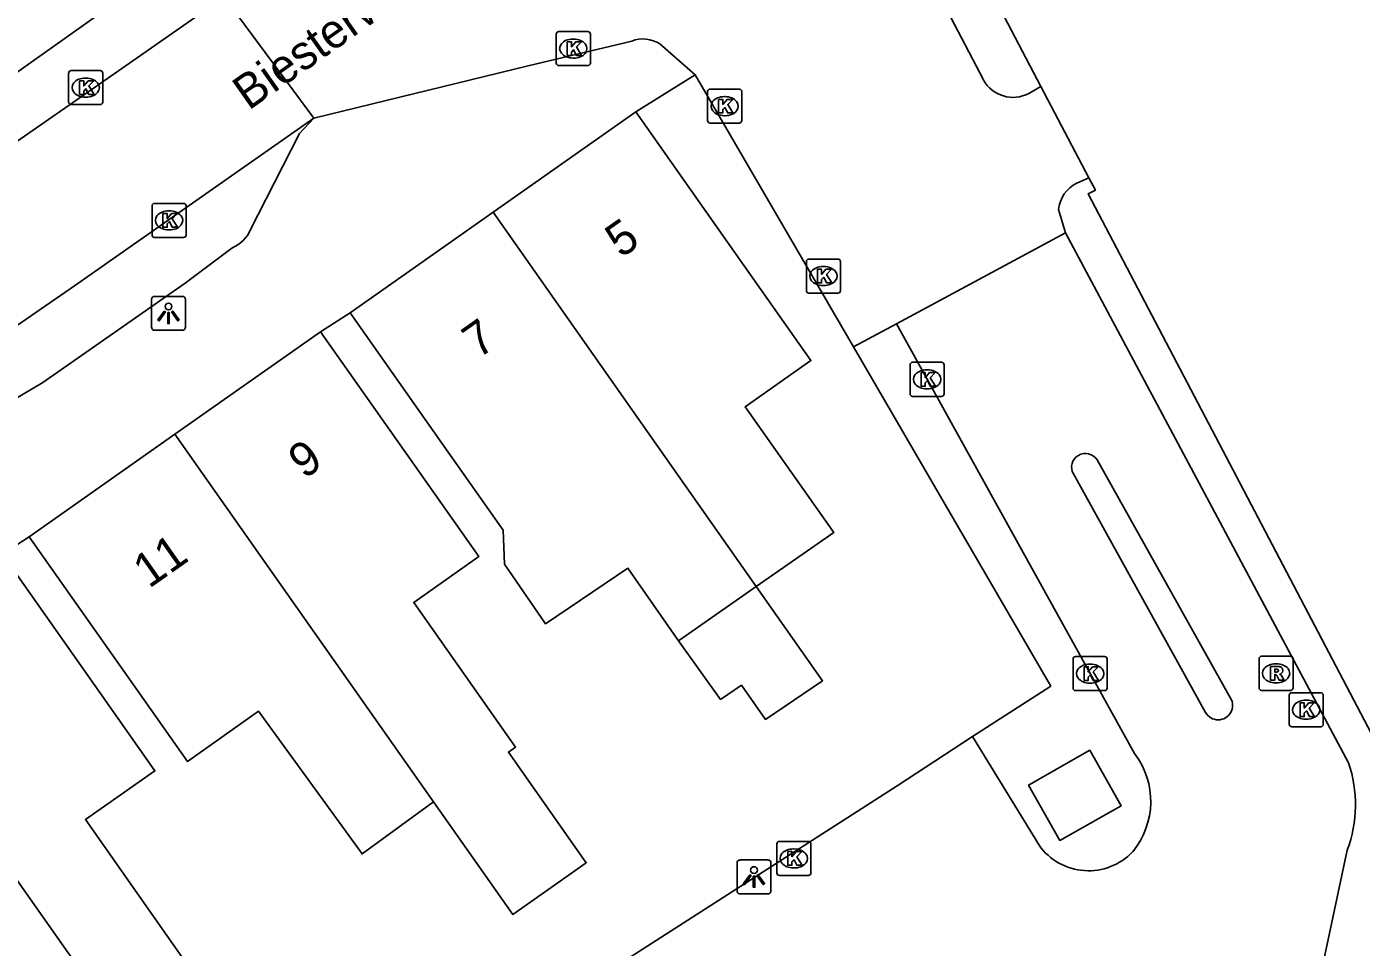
# Model space of a CAD drawing. Extents: x 161845 to 162341, y 381620 to 382158.
# Drawn here: x 162003.63 to 162042.81, y 381930.27 to 381957.3 of the extents above; entities that cross this region are included whole.
import ezdxf

# ---------------------------------------------------------------- set-up
doc = ezdxf.new("R2010")
doc.units = 0
for name, color, linetype in [('IMGEO_Kolk', 7, 'Continuous'), ('IMGEO_Lage_trafo', 7, 'Continuous'), ('IMGEO_Lichtpunt', 7, 'Continuous'), ('IMGEO_Muur', 7, 'Continuous'), ('IMGEO_Openbare_ruimte_label', 7, 'Continuous'), ('IMGEO_Pand', 7, 'Continuous'), ('IMGEO_Pand_nummerreeks', 7, 'Continuous'), ('IMGEO_Parkeervlak_gesloten', 7, 'Continuous'), ('IMGEO_Rijbaan_lokaal_open', 7, 'Continuous'), ('IMGEO_Rioolput', 7, 'Continuous'), ('IMGEO_Voetpad_open', 7, 'Continuous')]:
    doc.layers.add(name, color=color, linetype=linetype)

msp = doc.modelspace()

# ---------------------------------------------------------------- linework, layer by layer
at = {"layer": 'IMGEO_Kolk'}
for p, q in [((162019.176, 381956.233), (162019.176, 381957.085)), ((162019.251, 381957.159), (162020.103, 381957.159)), ((162019.664, 381956.939), (162019.689, 381956.939)), ((162020.177, 381957.085), (162020.177, 381956.233)), ((162020.103, 381956.159), (162019.251, 381956.159)), ((162019.687, 381956.379), (162019.662, 381956.379)), ((162004.859, 381955.087), (162004.859, 381955.939)), ((162004.934, 381956.013), (162005.786, 381956.013)), ((162005.347, 381955.793), (162005.372, 381955.793)), ((162005.86, 381955.939), (162005.86, 381955.087)), ((162023.62, 381954.542), (162023.62, 381955.394)), ((162023.695, 381955.468), (162024.547, 381955.468)), ((162024.621, 381955.394), (162024.621, 381954.542)), ((162005.786, 381955.013), (162004.934, 381955.013)), ((162005.37, 381955.233), (162005.345, 381955.233)), ((162024.108, 381955.248), (162024.133, 381955.248)), ((162024.131, 381954.688), (162024.106, 381954.688)), ((162024.547, 381954.468), (162023.695, 381954.468)), ((162007.308, 381951.187), (162007.308, 381952.039)), ((162007.383, 381952.113), (162008.235, 381952.113)), ((162007.796, 381951.893), (162007.821, 381951.893)), ((162008.309, 381952.039), (162008.309, 381951.187)), ((162008.235, 381951.113), (162007.383, 381951.113)), ((162007.819, 381951.333), (162007.794, 381951.333)), ((162026.521, 381949.554), (162026.521, 381950.406)), ((162026.596, 381950.48), (162027.448, 381950.48)), ((162027.009, 381950.26), (162027.034, 381950.26)), ((162027.522, 381950.406), (162027.522, 381949.554)), ((162027.448, 381949.48), (162026.596, 381949.48)), ((162027.032, 381949.7), (162027.007, 381949.7)), ((162029.565, 381946.521), (162029.565, 381947.373)), ((162029.64, 381947.447), (162030.492, 381947.447)), ((162030.053, 381947.227), (162030.078, 381947.227)), ((162030.566, 381947.373), (162030.566, 381946.521)), ((162030.492, 381946.447), (162029.64, 381946.447)), ((162030.076, 381946.667), (162030.051, 381946.667)), ((162034.351, 381937.882), (162034.351, 381938.734)), ((162034.426, 381938.808), (162035.278, 381938.808)), ((162034.839, 381938.588), (162034.864, 381938.588)), ((162035.352, 381938.734), (162035.352, 381937.882)), ((162035.278, 381937.808), (162034.426, 381937.808)), ((162034.862, 381938.028), (162034.837, 381938.028)), ((162040.77, 381937.748), (162041.622, 381937.748)), ((162040.695, 381936.822), (162040.695, 381937.674)), ((162041.183, 381937.528), (162041.208, 381937.528)), ((162041.696, 381937.674), (162041.696, 381936.822)), ((162041.206, 381936.968), (162041.181, 381936.968)), ((162041.622, 381936.748), (162040.77, 381936.748)), ((162025.726, 381933.381), (162026.578, 381933.381)), ((162025.651, 381932.455), (162025.651, 381933.307)), ((162026.139, 381933.161), (162026.164, 381933.161)), ((162026.652, 381933.307), (162026.652, 381932.455)), ((162026.162, 381932.601), (162026.137, 381932.601)), ((162026.578, 381932.381), (162025.726, 381932.381))]:
    msp.add_line(p, q, dxfattribs=at)
for points in [[(162019.176, 381956.233), (162019.176, 381957.085)], [(162019.251, 381957.159), (162020.103, 381957.159)], [(162020.177, 381957.085), (162020.177, 381956.233)], [(162019.497, 381956.859), (162019.62, 381956.859), (162019.62, 381956.708), (162019.75, 381956.859), (162019.914, 381956.859), (162019.768, 381956.708), (162019.921, 381956.459), (162019.769, 381956.459), (162019.684, 381956.623), (162019.62, 381956.556), (162019.62, 381956.459), (162019.497, 381956.459), (162019.497, 381956.859)], [(162020.103, 381956.159), (162019.251, 381956.159)], [(162004.859, 381955.087), (162004.859, 381955.939)], [(162004.934, 381956.013), (162005.786, 381956.013)], [(162005.86, 381955.939), (162005.86, 381955.087)], [(162005.18, 381955.713), (162005.303, 381955.713), (162005.303, 381955.562), (162005.433, 381955.713), (162005.597, 381955.713), (162005.451, 381955.562), (162005.604, 381955.313), (162005.452, 381955.313), (162005.367, 381955.477), (162005.303, 381955.41), (162005.303, 381955.313), (162005.18, 381955.313), (162005.18, 381955.713)], [(162023.62, 381954.542), (162023.62, 381955.394)], [(162023.695, 381955.468), (162024.547, 381955.468)], [(162024.621, 381955.394), (162024.621, 381954.542)], [(162005.786, 381955.013), (162004.934, 381955.013)], [(162023.941, 381955.168), (162024.064, 381955.168), (162024.064, 381955.017), (162024.194, 381955.168), (162024.358, 381955.168), (162024.212, 381955.017), (162024.365, 381954.768), (162024.213, 381954.768), (162024.128, 381954.932), (162024.064, 381954.865), (162024.064, 381954.768), (162023.941, 381954.768), (162023.941, 381955.168)], [(162024.547, 381954.468), (162023.695, 381954.468)], [(162007.308, 381951.187), (162007.308, 381952.039)], [(162007.383, 381952.113), (162008.235, 381952.113)], [(162007.629, 381951.813), (162007.752, 381951.813), (162007.752, 381951.662), (162007.882, 381951.813), (162008.046, 381951.813), (162007.9, 381951.662), (162008.053, 381951.413), (162007.901, 381951.413), (162007.816, 381951.577), (162007.752, 381951.51), (162007.752, 381951.413), (162007.629, 381951.413), (162007.629, 381951.813)], [(162008.309, 381952.039), (162008.309, 381951.187)], [(162008.235, 381951.113), (162007.383, 381951.113)], [(162026.521, 381949.554), (162026.521, 381950.406)], [(162026.596, 381950.48), (162027.448, 381950.48)], [(162027.522, 381950.406), (162027.522, 381949.554)], [(162026.842, 381950.18), (162026.965, 381950.18), (162026.965, 381950.029), (162027.095, 381950.18), (162027.259, 381950.18), (162027.113, 381950.029), (162027.266, 381949.78), (162027.114, 381949.78), (162027.029, 381949.944), (162026.965, 381949.877), (162026.965, 381949.78), (162026.842, 381949.78), (162026.842, 381950.18)], [(162027.448, 381949.48), (162026.596, 381949.48)], [(162029.565, 381946.521), (162029.565, 381947.373)], [(162029.64, 381947.447), (162030.492, 381947.447)], [(162029.886, 381947.147), (162030.009, 381947.147), (162030.009, 381946.996), (162030.139, 381947.147), (162030.303, 381947.147), (162030.157, 381946.996), (162030.31, 381946.747), (162030.158, 381946.747), (162030.073, 381946.911), (162030.009, 381946.844), (162030.009, 381946.747), (162029.886, 381946.747), (162029.886, 381947.147)], [(162030.566, 381947.373), (162030.566, 381946.521)], [(162030.492, 381946.447), (162029.64, 381946.447)], [(162034.351, 381937.882), (162034.351, 381938.734)], [(162034.426, 381938.808), (162035.278, 381938.808)], [(162034.672, 381938.508), (162034.795, 381938.508), (162034.795, 381938.357), (162034.925, 381938.508), (162035.089, 381938.508), (162034.943, 381938.357), (162035.096, 381938.108), (162034.944, 381938.108), (162034.859, 381938.272), (162034.795, 381938.205), (162034.795, 381938.108), (162034.672, 381938.108), (162034.672, 381938.508)], [(162035.352, 381938.734), (162035.352, 381937.882)], [(162035.278, 381937.808), (162034.426, 381937.808)], [(162040.77, 381937.748), (162041.622, 381937.748)], [(162040.695, 381936.822), (162040.695, 381937.674)], [(162041.016, 381937.448), (162041.139, 381937.448), (162041.139, 381937.297), (162041.269, 381937.448), (162041.433, 381937.448), (162041.287, 381937.297), (162041.44, 381937.048), (162041.288, 381937.048), (162041.203, 381937.212), (162041.139, 381937.145), (162041.139, 381937.048), (162041.016, 381937.048), (162041.016, 381937.448)], [(162041.696, 381937.674), (162041.696, 381936.822)], [(162041.622, 381936.748), (162040.77, 381936.748)], [(162025.726, 381933.381), (162026.578, 381933.381)], [(162025.651, 381932.455), (162025.651, 381933.307)], [(162025.972, 381933.081), (162026.095, 381933.081), (162026.095, 381932.93), (162026.225, 381933.081), (162026.389, 381933.081), (162026.243, 381932.93), (162026.396, 381932.681), (162026.244, 381932.681), (162026.159, 381932.845), (162026.095, 381932.778), (162026.095, 381932.681), (162025.972, 381932.681), (162025.972, 381933.081)], [(162026.652, 381933.307), (162026.652, 381932.455)], [(162026.578, 381932.381), (162025.726, 381932.381)]]:
    msp.add_lwpolyline(points, dxfattribs=at)
for centre, start, end in [((162019.253, 381957.083), 91.552, 178.448), ((162019.253, 381957.083), 91.552, 178.448), ((162020.101, 381957.083), 1.552, 88.448), ((162020.101, 381957.083), 1.552, 88.448), ((162019.253, 381956.235), 181.552, 268.448), ((162019.253, 381956.235), 181.552, 268.448), ((162020.101, 381956.235), 271.552, 358.448), ((162020.101, 381956.235), 271.552, 358.448), ((162004.936, 381955.937), 91.552, 178.448), ((162004.936, 381955.937), 91.552, 178.448), ((162005.784, 381955.937), 1.552, 88.448), ((162005.784, 381955.937), 1.552, 88.448), ((162023.697, 381955.392), 91.552, 178.448), ((162023.697, 381955.392), 91.552, 178.448), ((162024.545, 381955.392), 1.552, 88.448), ((162024.545, 381955.392), 1.552, 88.448), ((162004.936, 381955.089), 181.552, 268.448), ((162004.936, 381955.089), 181.552, 268.448), ((162005.784, 381955.089), 271.552, 358.448), ((162005.784, 381955.089), 271.552, 358.448), ((162023.697, 381954.544), 181.552, 268.448), ((162023.697, 381954.544), 181.552, 268.448), ((162024.545, 381954.544), 271.552, 358.448), ((162024.545, 381954.544), 271.552, 358.448), ((162007.385, 381952.037), 91.552, 178.448), ((162007.385, 381952.037), 91.552, 178.448), ((162008.233, 381952.037), 1.552, 88.448), ((162008.233, 381952.037), 1.552, 88.448), ((162007.385, 381951.189), 181.552, 268.448), ((162007.385, 381951.189), 181.552, 268.448), ((162008.233, 381951.189), 271.552, 358.448), ((162008.233, 381951.189), 271.552, 358.448), ((162026.598, 381950.404), 91.552, 178.448), ((162026.598, 381950.404), 91.552, 178.448), ((162027.446, 381950.404), 1.552, 88.448), ((162027.446, 381950.404), 1.552, 88.448), ((162026.598, 381949.556), 181.552, 268.448), ((162026.598, 381949.556), 181.552, 268.448), ((162027.446, 381949.556), 271.552, 358.448), ((162027.446, 381949.556), 271.552, 358.448), ((162029.642, 381947.371), 91.552, 178.448), ((162029.642, 381947.371), 91.552, 178.448), ((162030.49, 381947.371), 1.552, 88.448), ((162030.49, 381947.371), 1.552, 88.448), ((162029.642, 381946.523), 181.552, 268.448), ((162029.642, 381946.523), 181.552, 268.448), ((162030.49, 381946.523), 271.552, 358.448), ((162030.49, 381946.523), 271.552, 358.448), ((162034.428, 381938.732), 91.552, 178.448), ((162034.428, 381938.732), 91.552, 178.448), ((162035.276, 381938.732), 1.552, 88.448), ((162035.276, 381938.732), 1.552, 88.448), ((162034.428, 381937.884), 181.552, 268.448), ((162034.428, 381937.884), 181.552, 268.448), ((162035.276, 381937.884), 271.552, 358.448), ((162035.276, 381937.884), 271.552, 358.448), ((162040.772, 381937.672), 91.552, 178.448), ((162040.772, 381937.672), 91.552, 178.448), ((162041.62, 381937.672), 1.552, 88.448), ((162041.62, 381937.672), 1.552, 88.448), ((162040.772, 381936.824), 181.552, 268.448), ((162040.772, 381936.824), 181.552, 268.448), ((162041.62, 381936.824), 271.552, 358.448), ((162041.62, 381936.824), 271.552, 358.448), ((162025.728, 381933.305), 91.552, 178.448), ((162025.728, 381933.305), 91.552, 178.448), ((162026.576, 381933.305), 1.552, 88.448), ((162026.576, 381933.305), 1.552, 88.448), ((162025.728, 381932.457), 181.552, 268.448), ((162025.728, 381932.457), 181.552, 268.448), ((162026.576, 381932.457), 271.552, 358.448), ((162026.576, 381932.457), 271.552, 358.448)]:
    msp.add_arc(centre, 0.0765, start, end, dxfattribs=at)
for centre, major_axis, ratio, start_param, end_param in [((162019.663, 381956.659), (-0.387, 0.002), 0.722429, 4.712389, 7.853982), ((162019.688, 381956.659), (-0.39, 0.002), 0.717154, 1.570796, 4.712389), ((162005.346, 381955.513), (-0.387, 0.002), 0.722429, 4.712389, 7.853982), ((162005.371, 381955.513), (-0.39, 0.002), 0.717154, 1.570796, 4.712389), ((162024.107, 381954.968), (-0.387, 0.002), 0.722429, 4.712389, 7.853982), ((162024.132, 381954.968), (-0.39, 0.002), 0.717154, 1.570796, 4.712389), ((162007.795, 381951.613), (-0.387, 0.002), 0.722429, 4.712389, 7.853982), ((162007.82, 381951.613), (-0.39, 0.002), 0.717154, 1.570796, 4.712389), ((162027.008, 381949.98), (-0.387, 0.002), 0.722429, 4.712389, 7.853982), ((162027.033, 381949.98), (-0.39, 0.002), 0.717154, 1.570796, 4.712389), ((162030.052, 381946.947), (-0.387, 0.002), 0.722429, 4.712389, 7.853982), ((162030.077, 381946.947), (-0.39, 0.002), 0.717154, 1.570796, 4.712389), ((162034.838, 381938.308), (-0.387, 0.002), 0.722429, 4.712389, 7.853982), ((162034.863, 381938.308), (-0.39, 0.002), 0.717154, 1.570796, 4.712389), ((162041.182, 381937.248), (-0.387, 0.002), 0.722429, 4.712389, 7.853982), ((162041.207, 381937.248), (-0.39, 0.002), 0.717154, 1.570796, 4.712389), ((162026.138, 381932.881), (-0.387, 0.002), 0.722429, 4.712389, 7.853982), ((162026.163, 381932.881), (-0.39, 0.002), 0.717154, 1.570796, 4.712389)]:
    msp.add_ellipse(centre, major_axis=major_axis, ratio=ratio, start_param=start_param, end_param=end_param, dxfattribs=at)
at = {"layer": 'IMGEO_Lage_trafo'}
msp.add_lwpolyline([(162034.845, 381936.057), (162033.043, 381935.036), (162033.965, 381933.409), (162035.767, 381934.43), (162034.845, 381936.057)], dxfattribs=at)
at = {"layer": 'IMGEO_Lichtpunt'}
for p, q in [((162007.292, 381949.289), (162007.292, 381948.482)), ((162007.292, 381949.289), (162007.292, 381948.482)), ((162008.194, 381949.384), (162007.386, 381949.384)), ((162008.194, 381949.384), (162007.386, 381949.384)), ((162008.288, 381948.482), (162008.288, 381949.289)), ((162008.288, 381948.482), (162008.288, 381949.289)), ((162007.386, 381948.388), (162008.194, 381948.388)), ((162007.386, 381948.388), (162008.194, 381948.388)), ((162024.484, 381932.741), (162024.484, 381931.934)), ((162024.484, 381932.741), (162024.484, 381931.934)), ((162025.386, 381932.836), (162024.578, 381932.836)), ((162025.386, 381932.836), (162024.578, 381932.836)), ((162025.48, 381931.934), (162025.48, 381932.741)), ((162025.48, 381931.934), (162025.48, 381932.741)), ((162024.578, 381931.84), (162025.386, 381931.84)), ((162024.578, 381931.84), (162025.386, 381931.84))]:
    msp.add_line(p, q, dxfattribs=at)
for points in [[(162007.666, 381948.953), (162007.705, 381948.925), (162007.517, 381948.663), (162007.479, 381948.69), (162007.666, 381948.953)], [(162007.768, 381948.905), (162007.815, 381948.905), (162007.815, 381948.583), (162007.768, 381948.583), (162007.768, 381948.905)], [(162007.878, 381948.925), (162007.916, 381948.952), (162008.103, 381948.69), (162008.064, 381948.662), (162007.878, 381948.925)], [(162024.858, 381932.405), (162024.897, 381932.377), (162024.709, 381932.115), (162024.671, 381932.142), (162024.858, 381932.405)], [(162024.96, 381932.357), (162025.007, 381932.357), (162025.007, 381932.035), (162024.96, 381932.035), (162024.96, 381932.357)], [(162025.07, 381932.377), (162025.108, 381932.404), (162025.295, 381932.142), (162025.256, 381932.114), (162025.07, 381932.377)]]:
    msp.add_lwpolyline(points, dxfattribs=at)
for centre in [(162007.791, 381949.087), (162024.983, 381932.539)]:
    msp.add_circle(centre, 0.0994, dxfattribs=at)
for centre, start, end in [((162007.386, 381949.289), 90, 180), ((162007.386, 381949.289), 90, 180), ((162008.194, 381949.289), 0, 90), ((162008.194, 381949.289), 0, 90), ((162007.386, 381948.482), 180, 270), ((162007.386, 381948.482), 180, 270), ((162008.194, 381948.482), 270, 0), ((162008.194, 381948.482), 270, 360), ((162024.578, 381932.741), 90, 180), ((162024.578, 381932.741), 90, 180), ((162025.386, 381932.741), 0, 90), ((162025.386, 381932.741), 0, 90), ((162024.578, 381931.934), 180, 270), ((162024.578, 381931.934), 180, 270), ((162025.386, 381931.934), 270, 0), ((162025.386, 381931.934), 270, 360)]:
    msp.add_arc(centre, 0.0946, start, end, dxfattribs=at)
at = {"layer": 'IMGEO_Muur'}
for points in [[(162021.512, 381954.803), (162023.258, 381955.892)], [(162023.258, 381955.892), (162027.905, 381947.899)], [(162027.905, 381947.899), (162030.878, 381942.786)], [(162030.878, 381942.786), (162033.694, 381937.942), (162031.394, 381936.463)], [(162031.394, 381936.463), (162029.183, 381935.015)], [(162029.183, 381935.015), (162005.116, 381919.57)]]:
    msp.add_lwpolyline(points, dxfattribs=at)
at = {"layer": 'IMGEO_Pand'}
for points in [[(162033.406, 381955.541), (162031.141, 381959.872)], [(162034.815, 381952.864), (162033.406, 381955.541)], [(162021.512, 381954.803), (162017.319, 381951.851)], [(162021.512, 381954.803), (162024.39, 381950.715), (162026.653, 381947.499), (162024.727, 381946.143), (162027.323, 381942.455), (162025.05, 381940.863)], [(162044.575, 381936.811), (162043.321, 381936.152), (162034.793, 381952.391), (162035.005, 381952.503), (162034.815, 381952.864)], [(162013.126, 381948.899), (162017.319, 381951.851)], [(162017.319, 381951.851), (162025.05, 381940.863)], [(162022.77, 381939.266), (162021.281, 381941.399), (162018.864, 381939.765), (162017.659, 381941.525), (162017.618, 381942.518), (162016.004, 381944.81), (162013.126, 381948.899)], [(162012.252, 381948.345), (162007.975, 381945.335)], [(162012.252, 381948.345), (162015.131, 381944.257), (162016.901, 381941.742), (162014.991, 381940.397), (162017.981, 381936.15), (162017.771, 381936.003), (162020.056, 381932.756), (162017.9, 381931.238), (162015.574, 381934.541)], [(162007.975, 381945.335), (162003.702, 381942.327)], [(162015.574, 381934.541), (162007.975, 381945.335)], [(162015.574, 381934.541), (162013.474, 381933.016), (162010.434, 381937.203), (162008.344, 381935.732), (162006.58, 381938.239), (162003.702, 381942.327)], [(162002.916, 381941.812), (162005.794, 381937.723), (162007.393, 381935.452), (162005.352, 381934.022), (162008.461, 381929.604), (162006.277, 381928.066)], [(162025.05, 381940.863), (162022.77, 381939.266)], [(162022.77, 381939.266), (162024.003, 381937.552), (162024.614, 381937.964), (162025.317, 381936.965), (162026.995, 381938.096), (162025.05, 381940.863)], [(162006.277, 381928.066), (162005.398, 381929.314), (162000, 381936.981), (161998.693, 381938.837)]]:
    msp.add_lwpolyline(points, dxfattribs=at)
at = {"layer": 'IMGEO_Parkeervlak_gesloten'}
for points in [[(162038.974, 381937.59), (162035.054, 381944.58)], [(162034.36, 381944.17), (162038.243, 381937.165)], [(162005.116, 381919.57), (162029.183, 381935.015), (162031.394, 381936.463)]]:
    msp.add_lwpolyline(points, dxfattribs=at)
for centre, radius, start, end in [((162034.711, 381944.369), 0.403, 31.6065, 209.5409), ((162038.611, 381937.374), 0.423, 209.5718, 30.7752)]:
    msp.add_arc(centre, radius, start, end, dxfattribs=at)
at = {"layer": 'IMGEO_Rijbaan_lokaal_open'}
for points in [[(162009.423, 381958.174), (162005.452, 381955.402), (162000, 381951.624), (161974.917, 381936.979)], [(162012.054, 381954.611), (162009.423, 381958.174)], [(162031.719, 381955.736), (162030.327, 381958.403)], [(162012.054, 381954.611), (162018.349, 381956.152), (162021.392, 381956.878)], [(162022.22, 381956.797), (162023.258, 381955.892)], [(162027.905, 381947.899), (162023.258, 381955.892)], [(162033.406, 381955.541), (162033.051, 381955.344)], [(161994.71, 381943.316), (162000, 381946.422), (162001.768, 381947.455), (162005.028, 381949.695), (162012.054, 381954.611)], [(162034.458, 381952.709), (162034.815, 381952.864)], [(162034.127, 381951.245), (162033.923, 381951.933)], [(162029.163, 381948.576), (162034.127, 381951.245)], [(162027.905, 381947.899), (162029.163, 381948.576)]]:
    msp.add_lwpolyline(points, dxfattribs=at)
for centre, radius, start, end in [((162021.726, 381956.017), 0.923, 57.6372, 111.1883), ((162032.585, 381956.219), 0.992, 209.172, 298.0303), ((162034.9, 381951.832), 0.982, 116.7275, 174.1052)]:
    msp.add_arc(centre, radius, start, end, dxfattribs=at)
at = {"layer": 'IMGEO_Rioolput'}
for p, q in [((162039.811, 381937.89), (162039.811, 381938.742)), ((162039.886, 381938.816), (162040.738, 381938.816)), ((162040.299, 381938.596), (162040.324, 381938.596)), ((162040.812, 381938.742), (162040.812, 381937.89)), ((162040.738, 381937.816), (162039.886, 381937.816)), ((162040.322, 381938.036), (162040.297, 381938.036))]:
    msp.add_line(p, q, dxfattribs=at)
for points in [[(162039.811, 381937.89), (162039.811, 381938.742)], [(162039.886, 381938.816), (162040.738, 381938.816)], [(162040.4, 381938.514), (162040.148, 381938.516), (162040.148, 381938.116)], [(162040.812, 381938.742), (162040.812, 381937.89)], [(162040.148, 381938.116), (162040.272, 381938.116), (162040.272, 381938.278), (162040.283, 381938.278)], [(162040.326, 381938.435), (162040.272, 381938.435), (162040.272, 381938.354)], [(162040.272, 381938.354), (162040.324, 381938.354)], [(162040.33, 381938.249), (162040.401, 381938.116), (162040.541, 381938.116), (162040.476, 381938.242)], [(162040.738, 381937.816), (162039.886, 381937.816)]]:
    msp.add_lwpolyline(points, dxfattribs=at)
for centre, radius, start, end in [((162039.888, 381938.74), 0.0765, 91.552, 178.448), ((162039.888, 381938.74), 0.0765, 91.552, 178.448), ((162040.399, 381938.404), 0.109, 350.3612, 89.416), ((162040.736, 381938.74), 0.0765, 1.552, 88.448), ((162040.736, 381938.74), 0.0765, 1.552, 88.448), ((162040.282, 381938.225), 0.0533, 26.0293, 88.6989), ((162040.308, 381938.543), 0.19, 274.7715, 282.9687), ((162040.332, 381938.339), 0.0964, 77.0061, 93.1865), ((162040.346, 381938.396), 0.0378, 276.6634, 79.6772), ((162040.397, 381938.404), 0.112, 277.5842, 350.9817), ((162040.381, 381938.189), 0.108, 29.5134, 73.7905), ((162039.888, 381937.892), 0.0765, 181.552, 268.448), ((162039.888, 381937.892), 0.0765, 181.552, 268.448), ((162040.736, 381937.892), 0.0765, 271.552, 358.448), ((162040.736, 381937.892), 0.0765, 271.552, 358.448)]:
    msp.add_arc(centre, radius, start, end, dxfattribs=at)
for centre, major_axis, ratio, start_param, end_param in [((162040.298, 381938.316), (-0.387, 0.002), 0.722429, 4.712389, 7.853982), ((162040.323, 381938.316), (-0.39, 0.002), 0.717154, 1.570796, 4.712389)]:
    msp.add_ellipse(centre, major_axis=major_axis, ratio=ratio, start_param=start_param, end_param=end_param, dxfattribs=at)
at = {"layer": 'IMGEO_Voetpad_open'}
for points in [[(161972.911, 381937.782), (161973.533, 381938.154), (161982.723, 381943.483), (161999.035, 381952.878), (162000, 381953.557), (162002.756, 381955.558), (162009.295, 381960.196), (162009.22, 381960.309), (162018.131, 381966.571), (162019.209, 381965.048)], [(162023.258, 381955.892), (162021.512, 381954.803)], [(162010.203, 381951.351), (162010.661, 381952.251), (162011.637, 381954.169), (162012.054, 381954.611)], [(162042.441, 381935.689), (162034.127, 381951.245)], [(161998.22, 381943.376), (162000, 381944.43), (162004.1, 381946.856), (162008.28, 381949.774), (162009.649, 381950.802)], [(162013.126, 381948.899), (162012.252, 381948.345)], [(162029.163, 381948.576), (162036.152, 381935.962)], [(162031.394, 381936.463), (162033.694, 381937.942), (162030.878, 381942.786), (162027.905, 381947.899)], [(162003.702, 381942.327), (162002.916, 381941.812)], [(162033.352, 381933.267), (162031.394, 381936.463)], [(162041.474, 381928.798), (162042.402, 381933.125)]]:
    msp.add_lwpolyline(points, dxfattribs=at)
for centre, radius, start, end in [((162009.255, 381951.753), 1.029, 292.4802, 337.0003), ((162034.32, 381934.553), 2.312, 320.3658, 37.5682), ((162038.77, 381934.463), 3.871, 339.7843, 18.4729), ((162034.804, 381934.301), 1.782, 215.4631, 316.668)]:
    msp.add_arc(centre, radius, start, end, dxfattribs=at)

# ---------------------------------------------------------------- texts
at = {"layer": 'IMGEO_Openbare_ruimte_label'}
msp.add_text('Biesterweg', height=1, rotation=35.1845, dxfattribs=at).set_placement((162010.144, 381954.826))
at = {"layer": 'IMGEO_Pand_nummerreeks'}
for s, rotation, p in [('5', 35.1467, (162021.079, 381950.487)), ('7', 35.1452, (162016.885, 381947.535)), ('9', 35.1395, (162011.776, 381943.999)), ('11', 35.1395, (162007.218, 381940.791))]:
    msp.add_text(s, height=1, rotation=rotation, dxfattribs=at).set_placement(p)

doc.saveas('drawing.dxf')
